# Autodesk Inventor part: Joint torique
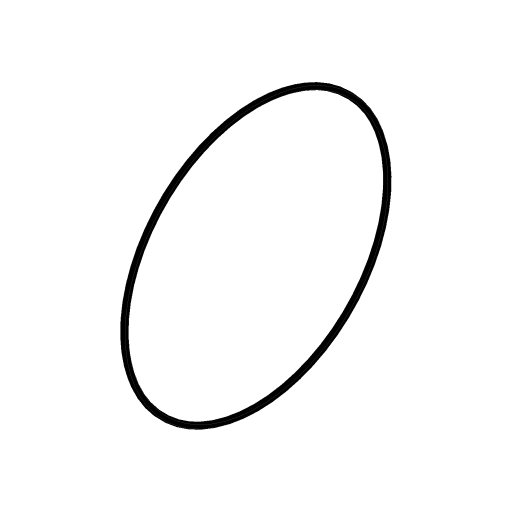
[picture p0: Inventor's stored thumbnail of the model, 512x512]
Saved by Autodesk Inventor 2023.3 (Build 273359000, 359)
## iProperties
Created: 2009-05
Part Number: Joint torique
Material: Générique
Document SubType Name: Modeling
Designer: TJ
Density: 1 g/cm^3
Appearance: Par défaut
Sending System: SolidWorks 2008
Last Author: Roger
Last Saved: 2011-02-17
Author: TJ
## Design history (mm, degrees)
feature "Enlèv. mat.-Extru.2"
node "Solide1"
